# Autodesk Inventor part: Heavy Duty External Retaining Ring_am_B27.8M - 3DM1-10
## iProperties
Shininess: 64.0
Length Units: 11269
Angle Units: 11279
Time Units: 11290
Mass Units: 11283
Length Display Precision: 3
Angle Display Precision: 2
Compacted: True
Part Number: Heavy Duty External Retaining Ring_am_B27.8M - 3DM1-10
Document SubType Name: Modeling
Created: 2006-11
Material: Par défaut
Designer: profs_sti
Density: 0.0
Volumn: 0.0
Area: 0.0
PropertySet Name: Model Information
Control State: 0
Master: False
Checked Out: False
Author: profs_sti
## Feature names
1. Base1
